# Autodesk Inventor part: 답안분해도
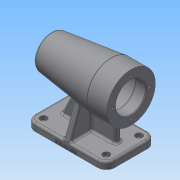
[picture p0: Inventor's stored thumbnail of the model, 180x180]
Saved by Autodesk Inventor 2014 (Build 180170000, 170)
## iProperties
Created: 2018-09
Part Number: 답안분해도
Material: 일반
Document SubType Name: Modeling
Designer: net
Density: 1 g/cm^3
Appearance: 기본값
Author: net
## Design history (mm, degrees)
sketch "스케치1"
  geometry: L1 (56, -34)-(-56, -34); L2 (-56, -34)-(-56, 34); L3 (-56, 34)-(56, 34); L4 (56, 34)-(56, -34); L5 (56, -34)-(-56, 34); L6 (-56, -34)-(56, 34); L7 (-28, 34)-(56, 23.686); L8 (50, 10.5)-(50, 0); L9 (50, 10.5)-(47, 10.5); L10 (47, 10.5)-(47, 0); L11 (47, 10.5)-(47, 16); L12 (47, 16)-(43, 16); L13 (43, 16)-(43, 0); L14 (43, 16)-(43, 17.5); L15 (43, 17.5)-(25, 17.5); L16 (25, 17.5)-(25, 0); L17 (25, 17.5)-(25, 21); L18 (25, 21)-(13, 21); L19 (13, 21)-(13, 0); L20 (13, 21)-(13, 24); L21 (13, 24)-(-41, 24); L22 (-41, 24)-(-41, 0); L23 (-41, 21)-(-56, 21); A1 r 80 centre (-20.413, 0) between (56, -23.686) and (56, 23.686); 4 further points
  constraints: 46 end point, 8 perpendicular, 5 point on line, 5 vertical, 4 collinear, 3 midpoint, 3 point on circle, 2 parallel, 1 centre point, 1 horizontal, 1 horizontal alignment, 10 other
  dimensions: "d0" = 112 distance of L2.end L3.end; "d1" = 28 distance from line of L2 L7.start; "d2" = 7 deg angle of L3 L7; "d3" = 68 dimension on L3; "d4" = 80 radius of A1; "d5" = 15 distance of L23.start L23.end; "d6" = 54 distance of L20.end L21.end; "d7" = 12 distance of L17.end L18.end; "d8" = 18 distance of L14.end L15.end; "d9" = 4 distance of L11.end L12.end; "d10" = 3 distance of L8.start L9.end; "d11" = 21 dimension on L9; "d12" = 32 dimension on L12; "d13" = 35 dimension on L15; "d14" = 42 dimension on L18; "d15" = 48 dimension on L21; "d16" = 42 dimension on L23
revolve "회전1" sketch "스케치1" stored, may be unused: angle "d17" = 90 deg
fillet "모깎기1" dims "d18" = 3
node "작업 평면1"
sketch "스케치2"
  geometry: L1 (-44, -35)-(44, -35); L2 (56, -23)-(56, 23); L3 (44, 35)-(-44, 35); L4 (-56, 23)-(-56, -23); L5 (-56, -35)-(56, 35); L6 (56, -35)-(-56, 35); A1 r 12 centre (-44, 23) between (-44, 35) and (-56, 23); A2 r 12 centre (-44, -23) between (-56, -23) and (-44, -35); A3 r 12 centre (44, -23) between (44, -35) and (56, -23); A4 r 12 centre (44, 23) between (56, 23) and (44, 35); 1 further point
  constraints: 12 end point, 8 point on circle, 8 point on line, 8 tangent, 4 centre point, 3 equal radius, 2 midpoint, 2 parallel, 1 horizontal, 1 perpendicular
  dimensions: "d20" = 112 distance of L5.end L6.end; "d21" = 70 distance of L6.start L5.end; "d22" = 12 radius of A1
extrude "돌출1" join sketch "스케치2" distance "d23" = 10; taper "d24" = 0 deg
sketch "스케치5"
  geometry: L1 (56, -23)-(56, 23) reference; L2 (-38, -4)-(38, -4); L3 (38, -4)-(38, 4); L4 (38, 4)-(-38, 4); L5 (-38, 4)-(-38, -4); L6 (-38, -4)-(38, 4); L7 (38, -4)-(-38, 4); 1 further point
  constraints: 12 end point, 2 midpoint, 2 parallel, 1 horizontal, 1 perpendicular
  dimensions: "d32" = 8 distance of L2.end L3.end; "d33" = 18 distance between parallel lines of L1 L3
extrude "돌출3" join sketch "스케치5" stored distance "d34" = 8; taper "d35" = 0 deg
feature "면 기울기1" dims angle "d36" = 25 deg
fillet "모깎기3" dims "d38" = 3
node "작업 평면2"
sketch "스케치18" dims "d62" = 52
  geometry: L1 (0, 0)-(-26, 0); C1 r 34 at (0, 0) reference; 1 further point
  constraints: 2 coincident, 2 end point, 1 horizontal, 1 horizontal alignment, 2 other
hole "구멍1" sketch "스케치18" at (-26, 0) diameter "d63" = 3.242; stored, may be unused: countersink angle "d67" = 90 deg, drill point angle "d69" = 118 deg; dims "d64" = 8, "d65" = 4, "d66" = 2, "d68" = 11
sketch "스케치20"
  geometry: L1 (35, -64)-(35, -74) reference; L2 (35, -74)-(-35, -74) reference; L3 (-35, -74)-(-35, -64) reference; L4 (-35, -64)-(-4, -64) reference; L5 (-4, -64)-(-4, -30.299) reference; L6 (4, -30.299)-(4, -64) reference; L7 (4, -64)-(35, -64) reference; L8 (-20.089, -23.032)-(-35, -64); C1 r 24 at (0, 0) reference; A1 r 30.562 centre (0, 0) between (4, -30.299) and (-4, -30.299) reference; 1 further point
  constraints: 2 end point, 1 point on circle
  dimensions: "d73" = 20 deg angle of L3 L8
extrude "돌출8" join sketch "스케치20" distance "d74" = 4; taper "d75" = 0 deg
node "작업 평면3"
sketch "스케치21"
  geometry: L1 (4, -64)-(35, -64) reference; L2 (35, -64)-(35, -74) reference; L3 (35, -74)-(-35, -74) reference; L4 (-35, -74)-(-35, -64) reference; L5 (-35, -64)-(-4, -64) reference; L6 (-4, -64)-(-4, -29.804) reference; L7 (4, -29.804)-(4, -64) reference; L8 (-19.909, -22.537)-(-35, -64); C1 r 24 at (0, 0) reference; A1 r 30.071 centre (0, 0) between (4, -29.804) and (-4, -29.804) reference; 1 further point
  constraints: 2 end point, 1 point on circle
  dimensions: "d77" = 20 deg angle of L8 L4
extrude "돌출9" join sketch "스케치21" distance "d78" = 4; taper "d79" = 0 deg
fillet "모깎기7" dims "d80" = 3
fillet "모깎기8" dims "d81" = 3
sketch "스케치22"
  geometry: C1 r 4.75 at (-44, 23); C2 r 2.75 at (-44, 23); C3 r 2.75 at (-44, -23); C4 r 4.75 at (-44, -23); A1 r 9 centre (-44, 23) between (-44, 32) and (-53, 23) reference; A2 r 9 centre (-44, -23) between (-53, -23) and (-44, -32) reference; 1 further point
  constraints: 4 centre point, 4 coincident
  dimensions: "d82" = 9.5 diameter of C1; "d83" = 5.5 diameter of C2; "d88" = 5.5 diameter of C3; "d89" = 9.5 diameter of C4
extrude "돌출10" cut sketch "스케치22" distance "d84" = 5.4; taper "d85" = 0 deg
extrude "돌출11" cut sketch "스케치22" stored distance "d86" = 5.4; taper "d87" = 0 deg
sketch "스케치23"
  geometry: C1 r 2.75 at (44, 23); C2 r 4.75 at (44, 23); C3 r 2.75 at (44, -23); C4 r 4.75 at (44, -23); A1 r 9 centre (44, -23) between (44, -32) and (53, -23) reference; A2 r 9 centre (44, 23) between (53, 23) and (44, 32) reference; 1 further point
  constraints: 4 centre point, 4 coincident
  dimensions: "d90" = 5.5 diameter of C1; "d91" = 9.5 diameter of C2; "d92" = 5.5 diameter of C3; "d93" = 9.5 diameter of C4
extrude "돌출12" cut sketch "스케치23" distance "d94" = 5.4; taper "d95" = 0 deg
extrude "돌출13" cut sketch "스케치23" stored distance "d96" = 5.4; taper "d97" = 0 deg
fillet "모깎기9" dims "d98" = 3, "d99" = 0.3
chamfer "모따기1" distance "d100" = 1; stored, may be unused: second distance "d101" = 2, angle "d102" = 45 deg
sketch "스케치24"
  geometry: L1 (88, 0)-(100, 0) reference; L2 (100, 0)-(100, 7) reference; 2 further points
  constraints: 1 other
  dimensions: "d103" = 3 distance from line of L1 point (44, 3); "d104" = 56 distance from line of L2 point (44, 3)
feature "엠보싱1" sketch "스케치24" dims "d0" = 112, "d1" = 28, "d2" = 7 deg, "d3" = 68, "d4" = 80, "d5" = 15, "d6" = 54, "d7" = 12, "d8" = 18, "d9" = 4, "d10" = 3, "d11" = 21, "d12" = 32, "d13" = 35, "d14" = 42, "d15" = 48, "d16" = 42, "d105" = 0.5, "d106" = 0
node "솔리드1"
pattern_circular "원형 패턴1" dims angle "d71" = 360 deg
mirror "대칭3"
node "절단 모서리 투영8"
node "절단 모서리 투영9"
other parameters: "d19" = -74, "d56" = -4, "d76" = -4
